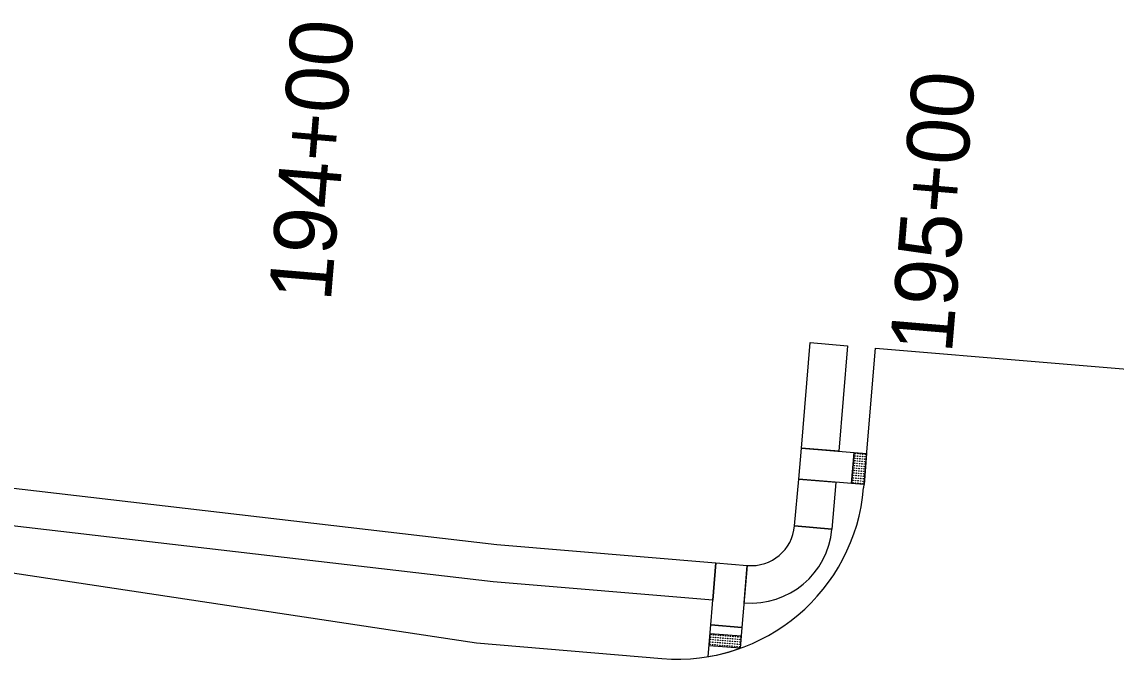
# Model space of a CAD drawing. Extents: x 20499216 to 20505321, y 7953487 to 7960535.
# Drawn here: x 20503065.2 to 20503240.7, y 7953795.2 to 7953897.4 of the extents above; entities that cross this region are included whole.
import ezdxf

# ---------------------------------------------------------------- set-up
doc = ezdxf.new("R2010")
doc.units = 0
for name, color, linetype in [('Drainage', 7, 'Continuous'), ('EXT_CU', 7, 'Continuous'), ('EXT_EG', 7, 'Continuous'), ('EXT_RR', 7, 'Continuous'), ('NamedBoundary', 7, 'Continuous'), ('Roadways', 7, 'Continuous'), ('Safety', 7, 'Continuous')]:
    doc.layers.add(name, color=color, linetype=linetype)

msp = doc.modelspace()

# ---------------------------------------------------------------- linework, layer by layer
at = {"layer": 'Drainage'}
msp.add_lwpolyline([(20503198.3, 7953823.36), (20503198.72, 7953828.34), (20503198.72, 7953828.34), (20503200.7, 7953828.17), (20503200.28, 7953823.19)], close=True, dxfattribs=at)
msp.add_lwpolyline([(20503175.29, 7953795.59), (20503175.71, 7953800.66), (20503180.7, 7953800.25), (20503180.43, 7953796.93)], dxfattribs=at)
msp.add_arc((20503170.31, 7953825.32), 30.14, 279.5178, 289.622, dxfattribs=at)
at = {"layer": 'EXT_CU'}
for p, q in [((20503198.3, 7953823.36), (20503198.71, 7953828.34)), ((20503198.71, 7953828.34), (20503200.7, 7953828.17)), ((20503200.7, 7953828.17), (20503200.29, 7953823.19)), ((20503200.29, 7953823.19), (20503198.3, 7953823.36)), ((20503189.15, 7953816.56), (20503195.13, 7953816.03)), ((20503175.44, 7953797.33), (20503175.61, 7953799.32)), ((20503175.61, 7953799.32), (20503180.59, 7953798.92)), ((20503180.59, 7953798.92), (20503180.43, 7953796.93)), ((20503180.43, 7953796.93), (20503175.44, 7953797.33))]:
    msp.add_line(p, q, dxfattribs=at)
for points in [[(20502662.5, 7953868.05), (20502961.27, 7953836.6), (20503020.68, 7953827.63), (20503141.39, 7953813.56), (20503176.54, 7953810.63), (20503176.04, 7953804.65), (20503140.79, 7953807.58), (20503019.89, 7953821.68), (20502960.51, 7953830.65), (20502661.92, 7953862.08), (20502601.24, 7953867.37), (20502601.76, 7953873.35)], [(20503197.65, 7953845.46), (20503196.24, 7953828.55), (20503190.26, 7953829.05), (20503191.67, 7953845.98), (20503197.65, 7953845.48)], [(20503195.79, 7953823.54), (20503195.13, 7953816.03), (20503189.15, 7953816.56), (20503189.82, 7953824.07), (20503195.8, 7953823.57)]]:
    msp.add_lwpolyline(points, close=True, dxfattribs=at)
msp.add_lwpolyline([(20503181.1, 7953804.23), (20503181.04, 7953804.23), (20503181.53, 7953810.21), (20503181.6, 7953810.21)], dxfattribs=at)
for radius in [13, 7]:
    msp.add_arc((20503182.18, 7953817.18), radius, 265.2365, 354.9395, dxfattribs=at)
for centre, major_axis in [((20503198.88, 7953827.79), (0.0243, -0.0287)), ((20503198.88, 7953827.79), (0.0121, -0.0143)), ((20503198.92, 7953828.18), (0.0243, -0.0287)), ((20503198.92, 7953828.18), (0.0121, -0.0143)), ((20503199.27, 7953827.76), (0.0243, -0.0287)), ((20503199.27, 7953827.76), (0.0121, -0.0143)), ((20503199.31, 7953828.15), (0.0243, -0.0287)), ((20503199.31, 7953828.15), (0.0121, -0.0143)), ((20503199.67, 7953827.72), (0.0243, -0.0287)), ((20503199.67, 7953827.72), (0.0121, -0.0143)), ((20503199.7, 7953828.12), (0.0243, -0.0287)), ((20503199.7, 7953828.12), (0.0121, -0.0143)), ((20503200.06, 7953827.69), (0.0243, -0.0287)), ((20503200.06, 7953827.69), (0.0121, -0.0143)), ((20503200.09, 7953828.08), (0.0243, -0.0287)), ((20503200.09, 7953828.08), (0.0121, -0.0143)), ((20503200.45, 7953827.66), (0.0243, -0.0287)), ((20503200.45, 7953827.66), (0.0121, -0.0143)), ((20503200.48, 7953828.05), (0.0243, -0.0287)), ((20503200.48, 7953828.05), (0.0121, -0.0143)), ((20503198.73, 7953825.84), (0.0243, -0.0287)), ((20503198.73, 7953825.84), (0.0121, -0.0143)), ((20503198.76, 7953826.23), (0.0243, -0.0287)), ((20503198.76, 7953826.23), (0.0121, -0.0143)), ((20503198.79, 7953826.62), (0.0243, -0.0287)), ((20503198.79, 7953826.62), (0.0121, -0.0143)), ((20503198.82, 7953827.01), (0.0243, -0.0287)), ((20503198.82, 7953827.01), (0.0121, -0.0143)), ((20503198.85, 7953827.4), (0.0243, -0.0287)), ((20503198.85, 7953827.4), (0.0121, -0.0143)), ((20503199.12, 7953825.81), (0.0243, -0.0287)), ((20503199.12, 7953825.81), (0.0121, -0.0143)), ((20503199.15, 7953826.2), (0.0243, -0.0287)), ((20503199.15, 7953826.2), (0.0121, -0.0143)), ((20503199.18, 7953826.59), (0.0243, -0.0287)), ((20503199.18, 7953826.59), (0.0121, -0.0143)), ((20503199.21, 7953826.98), (0.0243, -0.0287)), ((20503199.21, 7953826.98), (0.0121, -0.0143)), ((20503199.24, 7953827.37), (0.0243, -0.0287)), ((20503199.24, 7953827.37), (0.0121, -0.0143)), ((20503199.51, 7953825.77), (0.0243, -0.0287)), ((20503199.51, 7953825.77), (0.0121, -0.0143)), ((20503199.54, 7953826.16), (0.0243, -0.0287)), ((20503199.54, 7953826.16), (0.0121, -0.0143)), ((20503199.57, 7953826.55), (0.0243, -0.0287)), ((20503199.57, 7953826.55), (0.0121, -0.0143)), ((20503199.6, 7953826.94), (0.0243, -0.0287)), ((20503199.6, 7953826.94), (0.0121, -0.0143)), ((20503199.63, 7953827.33), (0.0243, -0.0287)), ((20503199.63, 7953827.33), (0.0121, -0.0143)), ((20503199.9, 7953825.74), (0.0243, -0.0287)), ((20503199.9, 7953825.74), (0.0121, -0.0143)), ((20503199.93, 7953826.13), (0.0243, -0.0287)), ((20503199.93, 7953826.13), (0.0121, -0.0143)), ((20503199.96, 7953826.52), (0.0243, -0.0287)), ((20503199.96, 7953826.52), (0.0121, -0.0143)), ((20503199.99, 7953826.91), (0.0243, -0.0287)), ((20503199.99, 7953826.91), (0.0121, -0.0143)), ((20503200.02, 7953827.3), (0.0243, -0.0287)), ((20503200.02, 7953827.3), (0.0121, -0.0143)), ((20503200.29, 7953825.71), (0.0243, -0.0287)), ((20503200.29, 7953825.71), (0.0121, -0.0143)), ((20503200.32, 7953826.1), (0.0243, -0.0287)), ((20503200.32, 7953826.1), (0.0121, -0.0143)), ((20503200.35, 7953826.49), (0.0243, -0.0287)), ((20503200.35, 7953826.49), (0.0121, -0.0143)), ((20503200.38, 7953826.88), (0.0243, -0.0287)), ((20503200.38, 7953826.88), (0.0121, -0.0143)), ((20503200.41, 7953827.27), (0.0243, -0.0287)), ((20503200.41, 7953827.27), (0.0121, -0.0143)), ((20503198.6, 7953824.26), (0.0243, -0.0287)), ((20503198.6, 7953824.26), (0.0121, -0.0143)), ((20503198.63, 7953824.67), (0.0243, -0.0287)), ((20503198.63, 7953824.67), (0.0121, -0.0143)), ((20503198.66, 7953825.06), (0.0243, -0.0287)), ((20503198.66, 7953825.06), (0.0121, -0.0143)), ((20503198.69, 7953825.45), (0.0243, -0.0287)), ((20503198.69, 7953825.45), (0.0121, -0.0143)), ((20503198.99, 7953824.22), (0.0243, -0.0287)), ((20503198.99, 7953824.22), (0.0121, -0.0143)), ((20503199.02, 7953824.64), (0.0243, -0.0287)), ((20503199.02, 7953824.64), (0.0121, -0.0143)), ((20503199.05, 7953825.03), (0.0243, -0.0287)), ((20503199.05, 7953825.03), (0.0121, -0.0143)), ((20503199.08, 7953825.42), (0.0243, -0.0287)), ((20503199.08, 7953825.42), (0.0121, -0.0143)), ((20503199.38, 7953824.19), (0.0243, -0.0287)), ((20503199.38, 7953824.19), (0.0121, -0.0143)), ((20503199.41, 7953824.6), (0.0243, -0.0287)), ((20503199.41, 7953824.6), (0.0121, -0.0143)), ((20503199.44, 7953824.99), (0.0243, -0.0287)), ((20503199.44, 7953824.99), (0.0121, -0.0143)), ((20503199.47, 7953825.38), (0.0243, -0.0287)), ((20503199.47, 7953825.38), (0.0121, -0.0143)), ((20503199.77, 7953824.16), (0.0243, -0.0287)), ((20503199.77, 7953824.16), (0.0121, -0.0143)), ((20503199.8, 7953824.57), (0.0243, -0.0287)), ((20503199.8, 7953824.57), (0.0121, -0.0143)), ((20503199.83, 7953824.96), (0.0243, -0.0287)), ((20503199.83, 7953824.96), (0.0121, -0.0143)), ((20503199.86, 7953825.35), (0.0243, -0.0287)), ((20503199.86, 7953825.35), (0.0121, -0.0143)), ((20503200.16, 7953824.13), (0.0243, -0.0287)), ((20503200.16, 7953824.13), (0.0121, -0.0143)), ((20503200.19, 7953824.54), (0.0243, -0.0287)), ((20503200.19, 7953824.54), (0.0121, -0.0143)), ((20503200.22, 7953824.93), (0.0243, -0.0287)), ((20503200.22, 7953824.93), (0.0121, -0.0143)), ((20503200.25, 7953825.32), (0.0243, -0.0287)), ((20503200.25, 7953825.32), (0.0121, -0.0143)), ((20503198.53, 7953823.48), (0.0243, -0.0287)), ((20503198.53, 7953823.48), (0.0121, -0.0143)), ((20503198.56, 7953823.87), (0.0243, -0.0287)), ((20503198.56, 7953823.87), (0.0121, -0.0143)), ((20503198.92, 7953823.44), (0.0243, -0.0287)), ((20503198.92, 7953823.44), (0.0121, -0.0143)), ((20503198.96, 7953823.83), (0.0243, -0.0287)), ((20503198.96, 7953823.83), (0.0121, -0.0143)), ((20503199.31, 7953823.41), (0.0243, -0.0287)), ((20503199.31, 7953823.41), (0.0121, -0.0143)), ((20503199.35, 7953823.8), (0.0243, -0.0287)), ((20503199.35, 7953823.8), (0.0121, -0.0143)), ((20503199.7, 7953823.38), (0.0243, -0.0287)), ((20503199.7, 7953823.38), (0.0121, -0.0143)), ((20503199.74, 7953823.77), (0.0243, -0.0287)), ((20503199.74, 7953823.77), (0.0121, -0.0143)), ((20503200.09, 7953823.34), (0.0243, -0.0287)), ((20503200.09, 7953823.34), (0.0121, -0.0143)), ((20503200.13, 7953823.73), (0.0243, -0.0287)), ((20503200.13, 7953823.73), (0.0121, -0.0143)), ((20503175.64, 7953797.93), (0.0286, 0.0243)), ((20503175.64, 7953797.93), (0.0143, 0.0121)), ((20503175.67, 7953798.32), (0.0286, 0.0243)), ((20503175.67, 7953798.32), (0.0143, 0.0121)), ((20503175.7, 7953798.71), (0.0286, 0.0243)), ((20503175.7, 7953798.71), (0.0143, 0.0121)), ((20503175.73, 7953799.1), (0.0286, 0.0243)), ((20503175.73, 7953799.1), (0.0143, 0.0121)), ((20503176.03, 7953797.9), (0.0286, 0.0243)), ((20503176.03, 7953797.9), (0.0143, 0.0121)), ((20503176.06, 7953798.29), (0.0286, 0.0243)), ((20503176.06, 7953798.29), (0.0143, 0.0121)), ((20503176.09, 7953798.68), (0.0286, 0.0243)), ((20503176.09, 7953798.68), (0.0143, 0.0121)), ((20503176.12, 7953799.07), (0.0286, 0.0243)), ((20503176.12, 7953799.07), (0.0143, 0.0121)), ((20503176.42, 7953797.87), (0.0286, 0.0243)), ((20503176.42, 7953797.87), (0.0143, 0.0121)), ((20503176.45, 7953798.26), (0.0286, 0.0243)), ((20503176.45, 7953798.26), (0.0143, 0.0121)), ((20503176.48, 7953798.65), (0.0286, 0.0243)), ((20503176.48, 7953798.65), (0.0143, 0.0121)), ((20503176.51, 7953799.04), (0.0286, 0.0243)), ((20503176.51, 7953799.04), (0.0143, 0.0121)), ((20503176.81, 7953797.84), (0.0286, 0.0243)), ((20503176.81, 7953797.84), (0.0143, 0.0121)), ((20503176.84, 7953798.23), (0.0286, 0.0243)), ((20503176.84, 7953798.23), (0.0143, 0.0121)), ((20503176.87, 7953798.62), (0.0286, 0.0243)), ((20503176.87, 7953798.62), (0.0143, 0.0121)), ((20503176.9, 7953799.01), (0.0286, 0.0243)), ((20503176.9, 7953799.01), (0.0143, 0.0121)), ((20503177.2, 7953797.8), (0.0286, 0.0243)), ((20503177.2, 7953797.8), (0.0143, 0.0121)), ((20503177.23, 7953798.2), (0.0286, 0.0243)), ((20503177.23, 7953798.2), (0.0143, 0.0121)), ((20503177.26, 7953798.59), (0.0286, 0.0243)), ((20503177.26, 7953798.59), (0.0143, 0.0121)), ((20503177.29, 7953798.98), (0.0286, 0.0243)), ((20503177.29, 7953798.98), (0.0143, 0.0121)), ((20503177.59, 7953797.77), (0.0286, 0.0243)), ((20503177.59, 7953797.77), (0.0143, 0.0121)), ((20503177.62, 7953798.16), (0.0286, 0.0243)), ((20503177.62, 7953798.16), (0.0143, 0.0121)), ((20503177.65, 7953798.55), (0.0286, 0.0243)), ((20503177.65, 7953798.55), (0.0143, 0.0121)), ((20503177.68, 7953798.94), (0.0286, 0.0243)), ((20503177.68, 7953798.94), (0.0143, 0.0121)), ((20503177.98, 7953797.74), (0.0286, 0.0243)), ((20503177.98, 7953797.74), (0.0143, 0.0121)), ((20503178.01, 7953798.13), (0.0286, 0.0243)), ((20503178.01, 7953798.13), (0.0143, 0.0121)), ((20503178.04, 7953798.52), (0.0286, 0.0243)), ((20503178.04, 7953798.52), (0.0143, 0.0121)), ((20503178.08, 7953798.91), (0.0286, 0.0243)), ((20503178.08, 7953798.91), (0.0143, 0.0121)), ((20503178.37, 7953797.71), (0.0286, 0.0243)), ((20503178.37, 7953797.71), (0.0143, 0.0121)), ((20503178.4, 7953798.1), (0.0286, 0.0243)), ((20503178.4, 7953798.1), (0.0143, 0.0121)), ((20503178.43, 7953798.49), (0.0286, 0.0243)), ((20503178.43, 7953798.49), (0.0143, 0.0121)), ((20503178.47, 7953798.88), (0.0286, 0.0243)), ((20503178.47, 7953798.88), (0.0143, 0.0121)), ((20503178.76, 7953797.68), (0.0286, 0.0243)), ((20503178.76, 7953797.68), (0.0143, 0.0121)), ((20503178.79, 7953798.07), (0.0286, 0.0243)), ((20503178.79, 7953798.07), (0.0143, 0.0121)), ((20503178.82, 7953798.46), (0.0286, 0.0243)), ((20503178.82, 7953798.46), (0.0143, 0.0121)), ((20503178.86, 7953798.85), (0.0286, 0.0243)), ((20503178.86, 7953798.85), (0.0143, 0.0121)), ((20503179.15, 7953797.65), (0.0286, 0.0243)), ((20503179.15, 7953797.65), (0.0143, 0.0121)), ((20503179.18, 7953798.04), (0.0286, 0.0243)), ((20503179.18, 7953798.04), (0.0143, 0.0121)), ((20503179.21, 7953798.43), (0.0286, 0.0243)), ((20503179.21, 7953798.43), (0.0143, 0.0121)), ((20503179.25, 7953798.82), (0.0286, 0.0243)), ((20503179.25, 7953798.82), (0.0143, 0.0121)), ((20503179.56, 7953797.61), (0.0286, 0.0243)), ((20503179.56, 7953797.61), (0.0143, 0.0121)), ((20503179.59, 7953798), (0.0286, 0.0243)), ((20503179.59, 7953798), (0.0143, 0.0121)), ((20503179.62, 7953798.4), (0.0286, 0.0243)), ((20503179.62, 7953798.4), (0.0143, 0.0121)), ((20503179.66, 7953798.79), (0.0286, 0.0243)), ((20503179.66, 7953798.79), (0.0143, 0.0121)), ((20503179.98, 7953797.97), (0.0286, 0.0243)), ((20503179.98, 7953797.97), (0.0143, 0.0121)), ((20503180.02, 7953798.36), (0.0286, 0.0243)), ((20503180.02, 7953798.36), (0.0143, 0.0121)), ((20503180.05, 7953798.75), (0.0286, 0.0243)), ((20503180.05, 7953798.75), (0.0143, 0.0121)), ((20503180.37, 7953797.94), (0.0286, 0.0243)), ((20503180.37, 7953797.94), (0.0143, 0.0121)), ((20503180.41, 7953798.33), (0.0286, 0.0243)), ((20503180.41, 7953798.33), (0.0143, 0.0121)), ((20503180.44, 7953798.72), (0.0286, 0.0243)), ((20503180.44, 7953798.72), (0.0143, 0.0121)), ((20503175.6, 7953797.54), (0.0286, 0.0243)), ((20503175.6, 7953797.54), (0.0143, 0.0121)), ((20503175.99, 7953797.51), (0.0286, 0.0243)), ((20503175.99, 7953797.51), (0.0143, 0.0121)), ((20503176.38, 7953797.48), (0.0286, 0.0243)), ((20503176.38, 7953797.48), (0.0143, 0.0121)), ((20503176.77, 7953797.45), (0.0286, 0.0243)), ((20503176.77, 7953797.45), (0.0143, 0.0121)), ((20503177.16, 7953797.41), (0.0286, 0.0243)), ((20503177.16, 7953797.41), (0.0143, 0.0121)), ((20503177.55, 7953797.38), (0.0286, 0.0243)), ((20503177.55, 7953797.38), (0.0143, 0.0121)), ((20503177.94, 7953797.35), (0.0286, 0.0243)), ((20503177.94, 7953797.35), (0.0143, 0.0121)), ((20503178.34, 7953797.32), (0.0286, 0.0243)), ((20503178.34, 7953797.32), (0.0143, 0.0121)), ((20503178.73, 7953797.29), (0.0286, 0.0243)), ((20503178.73, 7953797.29), (0.0143, 0.0121)), ((20503179.12, 7953797.26), (0.0286, 0.0243)), ((20503179.12, 7953797.26), (0.0143, 0.0121)), ((20503179.53, 7953797.22), (0.0286, 0.0243)), ((20503179.53, 7953797.22), (0.0143, 0.0121)), ((20503179.92, 7953797.19), (0.0286, 0.0243)), ((20503179.92, 7953797.19), (0.0143, 0.0121)), ((20503179.95, 7953797.58), (0.0286, 0.0243)), ((20503179.95, 7953797.58), (0.0143, 0.0121)), ((20503180.31, 7953797.16), (0.0286, 0.0243)), ((20503180.31, 7953797.16), (0.0143, 0.0121)), ((20503180.34, 7953797.55), (0.0286, 0.0243)), ((20503180.34, 7953797.55), (0.0143, 0.0121))]:
    msp.add_ellipse(centre, major_axis=major_axis, ratio=0.997282, dxfattribs=at)
at = {"layer": 'EXT_EG'}
msp.add_line((20503175.71, 7953800.66), (20503180.7, 7953800.25), dxfattribs=at)
at = {"layer": 'NamedBoundary'}
for points in [[(20502611.92, 7953860.41), (20502661.35, 7953856.11), (20502959.75, 7953824.69), (20503138.13, 7953797.77), (20503167.85, 7953795.29), (20503167.85, 7953795.29)], [(20503200.24, 7953822.66), (20503202.13, 7953845.11), (20503255.94, 7953840.58), (20503255.01, 7953829.56), (20503255.01, 7953829.56)]]:
    msp.add_lwpolyline(points, dxfattribs=at)
msp.add_arc((20503170.34, 7953825.18), 30, 265.2301, 355.1856, dxfattribs=at)
at = {"layer": 'Roadways'}
msp.add_lwpolyline([(20503198.72, 7953828.34), (20503198.3, 7953823.36), (20503189.82, 7953824.07), (20503190.26, 7953829.05)], close=True, dxfattribs=at)
msp.add_lwpolyline([(20503181.53, 7953810.21), (20503180.7, 7953800.25), (20503175.71, 7953800.66), (20503176.54, 7953810.63), (20503181.52, 7953810.21)], dxfattribs=at)
msp.add_arc((20503182.1, 7953817.17), 6.99, 265.2364, 265.3147, dxfattribs=at)

# ---------------------------------------------------------------- texts
at = {"layer": 'EXT_RR'}
for s, p in [('194+00', (20503114.72, 7953852.41)), ('195+00', (20503214.38, 7953844.1))]:
    msp.add_text(s, height=10.02, rotation=85.2296, dxfattribs=at).set_placement(p)
at = {"layer": 'Safety'}
msp.add_text('195+00', height=10.02, rotation=85.2296, dxfattribs=at).set_placement((20503214.38, 7953844.1))

doc.saveas('drawing.dxf')
